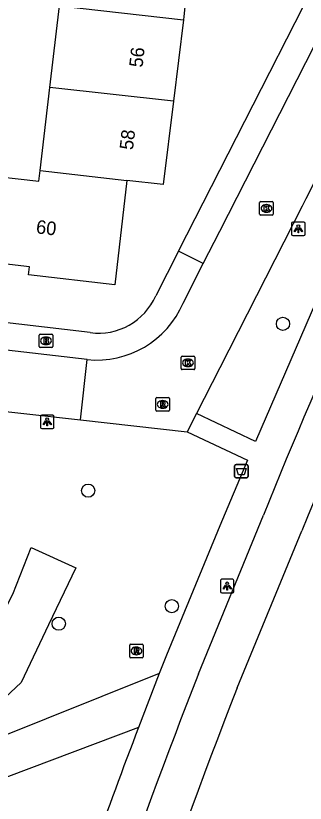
# Model space of a CAD drawing. Extents: x 161243 to 161752, y 384138 to 384885.
# Drawn here: x 161484.9 to 161506.3, y 384311.1 to 384369.4 of the extents above; entities that cross this region are included whole.
import ezdxf

# ---------------------------------------------------------------- set-up
doc = ezdxf.new("R2010")
doc.units = 0
for name, color, linetype in [('IMGEO_Afvalbak', 7, 'Continuous'), ('IMGEO_Boom', 7, 'Continuous'), ('IMGEO_Brandkraan', 7, 'Continuous'), ('IMGEO_Fietspad_gesloten', 7, 'Continuous'), ('IMGEO_Groenvoorziening', 7, 'Continuous'), ('IMGEO_Kolk', 7, 'Continuous'), ('IMGEO_Lichtpunt', 7, 'Continuous'), ('IMGEO_Pand', 7, 'Continuous'), ('IMGEO_Pand_nummerreeks', 7, 'Continuous'), ('IMGEO_Parkeervlak_open', 7, 'Continuous'), ('IMGEO_Rijbaan_lokaal_gesloten', 7, 'Continuous'), ('IMGEO_Rijbaan_lokaal_open', 7, 'Continuous'), ('IMGEO_Rioolput', 7, 'Continuous'), ('IMGEO_Voetpad_open', 7, 'Continuous')]:
    doc.layers.add(name, color=color, linetype=linetype)

msp = doc.modelspace()

# ---------------------------------------------------------------- linework, layer by layer
at = {"layer": 'IMGEO_Afvalbak'}
for p, q in [((161501.203, 384336.168), (161501.993, 384336.168)), ((161501.993, 384336.168), (161501.203, 384336.168)), ((161501.103, 384335.268), (161501.103, 384336.068)), ((161501.103, 384336.068), (161501.103, 384335.268)), ((161502.093, 384336.068), (161502.093, 384335.268)), ((161502.093, 384335.268), (161502.093, 384336.068)), ((161501.993, 384335.168), (161501.203, 384335.168)), ((161501.203, 384335.168), (161501.993, 384335.168))]:
    msp.add_line(p, q, dxfattribs=at)
msp.add_lwpolyline([(161501.246, 384335.882), (161501.95, 384335.882), (161501.801, 384335.412), (161501.395, 384335.412), (161501.246, 384335.882)], dxfattribs=at)
for centre, start, end in [((161501.203, 384336.068), 90, 180), ((161501.203, 384336.068), 90, 180), ((161501.993, 384336.068), 0, 90), ((161501.993, 384336.068), 360, 90), ((161501.203, 384335.268), 180, 270), ((161501.203, 384335.268), 180, 270), ((161501.993, 384335.268), 270, 0), ((161501.993, 384335.268), 270, 0)]:
    msp.add_arc(centre, 0.1, start, end, dxfattribs=at)
at = {"layer": 'IMGEO_Boom'}
for centre in [(161504.673, 384346.583), (161490.279, 384334.23), (161496.455, 384325.679), (161488.101, 384324.381)]:
    msp.add_circle(centre, 0.489, dxfattribs=at)
at = {"layer": 'IMGEO_Brandkraan'}
for p, q in [((161486.654, 384344.898), (161486.654, 384345.75)), ((161486.729, 384345.824), (161487.581, 384345.824)), ((161487.142, 384345.604), (161487.167, 384345.604)), ((161487.655, 384345.75), (161487.655, 384344.898)), ((161487.165, 384345.044), (161487.14, 384345.044)), ((161487.581, 384344.824), (161486.729, 384344.824))]:
    msp.add_line(p, q, dxfattribs=at)
for points in [[(161486.654, 384344.898), (161486.654, 384345.75)], [(161486.729, 384345.824), (161487.581, 384345.824)], [(161487.002, 384345.524), (161487.002, 384345.124), (161487.215, 384345.124)], [(161487.233, 384345.524), (161487.002, 384345.524)], [(161487.181, 384345.443), (161487.127, 384345.443), (161487.127, 384345.367)], [(161487.655, 384345.75), (161487.655, 384344.898)], [(161487.127, 384345.367), (161487.18, 384345.367)], [(161487.189, 384345.291), (161487.127, 384345.291), (161487.127, 384345.21)], [(161487.127, 384345.21), (161487.189, 384345.21)], [(161487.581, 384344.824), (161486.729, 384344.824)]]:
    msp.add_lwpolyline(points, dxfattribs=at)
for centre, radius, start, end in [((161486.731, 384345.748), 0.0765, 91.55205, 178.44795), ((161486.731, 384345.748), 0.0765, 91.55205, 178.44795), ((161487.182, 384345.405), 0.0379, 267.82845, 90.93552), ((161487.237, 384345.379), 0.145, 59.4692, 91.53667), ((161487.262, 384345.426), 0.0922, 285.51372, 58.15012), ((161487.579, 384345.748), 0.0765, 1.55205, 88.44795), ((161487.579, 384345.748), 0.0765, 1.55205, 88.44795), ((161486.731, 384344.9), 0.0765, 181.55205, 268.44795), ((161486.731, 384344.9), 0.0765, 181.55205, 268.44795), ((161487.19, 384345.25), 0.0404, 269.87594, 90.50774), ((161487.221, 384345.375), 0.251, 268.66757, 293.53466), ((161487.267, 384345.234), 0.105, 301.31148, 78.98903), ((161487.579, 384344.9), 0.0765, 271.55205, 358.44795), ((161487.579, 384344.9), 0.0765, 271.55205, 358.44795)]:
    msp.add_arc(centre, radius, start, end, dxfattribs=at)
for centre, major_axis, ratio, start_param, end_param in [((161487.141, 384345.324), (-0.387, 0.002), 0.722429, 4.712389, 7.853982), ((161487.166, 384345.324), (-0.39, 0.002), 0.717154, 1.570796, 4.712389)]:
    msp.add_ellipse(centre, major_axis=major_axis, ratio=ratio, start_param=start_param, end_param=end_param, dxfattribs=at)
at = {"layer": 'IMGEO_Fietspad_gesloten'}
for points in [[(161498.421, 384320.674), (161503.228, 384332.423)], [(161501.29, 384319.627), (161506.068, 384331.252)]]:
    msp.add_lwpolyline(points, dxfattribs=at)
for centre, radius, start, end in [((161887.469, 384177.749), 414.204, 153.12097, 158.07301), ((161885.987, 384179.087), 409.259, 153.19423, 158.17289), ((162043.129, 384109.325), 584.273, 158.793501, 162.628481), ((162039.774, 384110.274), 577.749, 158.754785, 167.348346)]:
    msp.add_arc(centre, radius, start, end, dxfattribs=at)
at = {"layer": 'IMGEO_Groenvoorziening'}
msp.add_lwpolyline([(161470.006, 384315.1), (161477.282, 384317.376), (161480.989, 384319.99), (161482.257, 384321.848), (161484.717, 384326.566), (161486.057, 384330.033), (161489.36, 384328.528), (161487.354, 384324.306), (161485.323, 384320.031), (161483.727, 384318.556), (161477.373, 384315.107), (161470.293, 384313.473), (161463.848, 384312.52), (161458.031, 384313.16), (161455.665, 384312.818), (161451.642, 384312.465), (161447.518, 384311.722)], dxfattribs=at)
at = {"layer": 'IMGEO_Kolk'}
for p, q in [((161502.951, 384354.704), (161502.951, 384355.556)), ((161503.026, 384355.63), (161503.878, 384355.63)), ((161503.439, 384355.41), (161503.464, 384355.41)), ((161503.952, 384355.556), (161503.952, 384354.704)), ((161503.462, 384354.85), (161503.437, 384354.85)), ((161503.878, 384354.63), (161503.026, 384354.63)), ((161497.15, 384343.265), (161497.15, 384344.117)), ((161497.225, 384344.191), (161498.077, 384344.191)), ((161497.638, 384343.971), (161497.663, 384343.971)), ((161498.151, 384344.117), (161498.151, 384343.265)), ((161498.077, 384343.191), (161497.225, 384343.191)), ((161497.661, 384343.411), (161497.636, 384343.411))]:
    msp.add_line(p, q, dxfattribs=at)
for points in [[(161502.951, 384354.704), (161502.951, 384355.556)], [(161503.026, 384355.63), (161503.878, 384355.63)], [(161503.952, 384355.556), (161503.952, 384354.704)], [(161503.272, 384355.33), (161503.395, 384355.33), (161503.395, 384355.179), (161503.525, 384355.33), (161503.689, 384355.33), (161503.543, 384355.179), (161503.696, 384354.93), (161503.544, 384354.93), (161503.459, 384355.094), (161503.395, 384355.027), (161503.395, 384354.93), (161503.272, 384354.93), (161503.272, 384355.33)], [(161503.878, 384354.63), (161503.026, 384354.63)], [(161497.15, 384343.265), (161497.15, 384344.117)], [(161497.225, 384344.191), (161498.077, 384344.191)], [(161497.471, 384343.891), (161497.594, 384343.891), (161497.594, 384343.74), (161497.724, 384343.891), (161497.888, 384343.891), (161497.742, 384343.74), (161497.895, 384343.491), (161497.743, 384343.491), (161497.658, 384343.655), (161497.594, 384343.588), (161497.594, 384343.491), (161497.471, 384343.491), (161497.471, 384343.891)], [(161498.151, 384344.117), (161498.151, 384343.265)], [(161498.077, 384343.191), (161497.225, 384343.191)]]:
    msp.add_lwpolyline(points, dxfattribs=at)
for centre, start, end in [((161503.028, 384355.554), 91.55205, 178.44795), ((161503.028, 384355.554), 91.55205, 178.44795), ((161503.876, 384355.554), 1.55205, 88.44795), ((161503.876, 384355.554), 1.55205, 88.44795), ((161503.028, 384354.706), 181.55205, 268.44795), ((161503.028, 384354.706), 181.55205, 268.44795), ((161503.876, 384354.706), 271.55205, 358.44795), ((161503.876, 384354.706), 271.55205, 358.44795), ((161497.227, 384344.115), 91.55205, 178.44795), ((161497.227, 384344.115), 91.55205, 178.44795), ((161498.075, 384344.115), 1.55205, 88.44795), ((161498.075, 384344.115), 1.55205, 88.44795), ((161497.227, 384343.267), 181.55205, 268.44795), ((161497.227, 384343.267), 181.55205, 268.44795), ((161498.075, 384343.267), 271.55205, 358.44795), ((161498.075, 384343.267), 271.55205, 358.44795)]:
    msp.add_arc(centre, 0.0765, start, end, dxfattribs=at)
for centre, major_axis, ratio, start_param, end_param in [((161503.438, 384355.13), (-0.387, 0.002), 0.722429, 4.712389, 7.853982), ((161503.463, 384355.13), (-0.39, 0.002), 0.717154, 1.570796, 4.712389), ((161497.637, 384343.691), (-0.387, 0.002), 0.722429, 4.712389, 7.853982), ((161497.662, 384343.691), (-0.39, 0.002), 0.717154, 1.570796, 4.712389)]:
    msp.add_ellipse(centre, major_axis=major_axis, ratio=ratio, start_param=start_param, end_param=end_param, dxfattribs=at)
at = {"layer": 'IMGEO_Lichtpunt'}
for p, q in [((161505.311, 384354.016), (161505.311, 384353.209)), ((161505.311, 384354.016), (161505.311, 384353.209)), ((161506.213, 384354.111), (161505.405, 384354.111)), ((161506.213, 384354.111), (161505.405, 384354.111)), ((161506.307, 384353.209), (161506.307, 384354.016)), ((161506.307, 384353.209), (161506.307, 384354.016)), ((161505.405, 384353.115), (161506.213, 384353.115)), ((161505.405, 384353.115), (161506.213, 384353.115)), ((161486.754, 384339.725), (161486.754, 384338.918)), ((161486.754, 384339.725), (161486.754, 384338.918)), ((161487.656, 384339.82), (161486.848, 384339.82)), ((161487.656, 384339.82), (161486.848, 384339.82)), ((161487.75, 384338.918), (161487.75, 384339.725)), ((161487.75, 384338.918), (161487.75, 384339.725)), ((161486.848, 384338.824), (161487.656, 384338.824)), ((161486.848, 384338.824), (161487.656, 384338.824)), ((161500.055, 384327.572), (161500.055, 384326.765)), ((161500.055, 384327.572), (161500.055, 384326.765)), ((161500.957, 384327.667), (161500.149, 384327.667)), ((161500.957, 384327.667), (161500.149, 384327.667)), ((161501.051, 384326.765), (161501.051, 384327.572)), ((161501.051, 384326.765), (161501.051, 384327.572)), ((161500.149, 384326.671), (161500.957, 384326.671)), ((161500.149, 384326.671), (161500.957, 384326.671))]:
    msp.add_line(p, q, dxfattribs=at)
for points in [[(161505.685, 384353.68), (161505.724, 384353.652), (161505.536, 384353.39), (161505.498, 384353.417), (161505.685, 384353.68)], [(161505.787, 384353.632), (161505.834, 384353.632), (161505.834, 384353.31), (161505.787, 384353.31), (161505.787, 384353.632)], [(161505.897, 384353.652), (161505.935, 384353.679), (161506.122, 384353.417), (161506.083, 384353.389), (161505.897, 384353.652)], [(161487.128, 384339.389), (161487.167, 384339.361), (161486.979, 384339.099), (161486.941, 384339.126), (161487.128, 384339.389)], [(161487.23, 384339.341), (161487.277, 384339.341), (161487.277, 384339.019), (161487.23, 384339.019), (161487.23, 384339.341)], [(161487.34, 384339.361), (161487.378, 384339.388), (161487.565, 384339.126), (161487.526, 384339.098), (161487.34, 384339.361)], [(161500.429, 384327.236), (161500.468, 384327.208), (161500.28, 384326.946), (161500.242, 384326.973), (161500.429, 384327.236)], [(161500.531, 384327.188), (161500.578, 384327.188), (161500.578, 384326.866), (161500.531, 384326.866), (161500.531, 384327.188)], [(161500.641, 384327.208), (161500.679, 384327.235), (161500.866, 384326.973), (161500.827, 384326.945), (161500.641, 384327.208)]]:
    msp.add_lwpolyline(points, dxfattribs=at)
for centre in [(161505.81, 384353.814), (161487.253, 384339.523), (161500.554, 384327.37)]:
    msp.add_circle(centre, 0.0994, dxfattribs=at)
for centre, start, end in [((161505.405, 384354.016), 90, 180), ((161505.405, 384354.016), 90, 180), ((161506.213, 384354.016), 0, 90), ((161506.213, 384354.016), 0, 90), ((161505.405, 384353.209), 180, 270), ((161505.405, 384353.209), 180, 270), ((161506.213, 384353.209), 270, 0), ((161506.213, 384353.209), 270, 360), ((161486.848, 384339.725), 90, 180), ((161486.848, 384339.725), 90, 180), ((161487.656, 384339.725), 0, 90), ((161487.656, 384339.725), 0, 90), ((161486.848, 384338.918), 180, 270), ((161486.848, 384338.918), 180, 270), ((161487.656, 384338.918), 270, 0), ((161487.656, 384338.918), 270, 360), ((161500.149, 384327.572), 90, 180), ((161500.149, 384327.572), 90, 180), ((161500.957, 384327.572), 0, 90), ((161500.957, 384327.572), 0, 90), ((161500.149, 384326.765), 180, 270), ((161500.149, 384326.765), 180, 270), ((161500.957, 384326.765), 270, 0), ((161500.957, 384326.765), 270, 360)]:
    msp.add_arc(centre, 0.0946, start, end, dxfattribs=at)
at = {"layer": 'IMGEO_Pand'}
for points in [[(161488.879, 384376.277), (161492.977, 384375.8), (161497.943, 384375.221), (161497.358, 384369.338), (161497.328, 384369.093)], [(161487.449, 384364.089), (161488.158, 384370.128)], [(161488.158, 384370.128), (161497.328, 384369.093)], [(161497.328, 384369.093), (161496.586, 384363.058)], [(161486.727, 384357.934), (161487.449, 384364.089)], [(161496.586, 384363.058), (161487.449, 384364.089)], [(161496.586, 384363.058), (161495.828, 384356.898), (161493.144, 384357.205)], [(161482.243, 384357.65), (161486.633, 384357.135), (161486.727, 384357.934)], [(161486.727, 384357.934), (161493.144, 384357.205)], [(161493.144, 384357.205), (161492.248, 384349.474), (161485.872, 384350.207), (161485.928, 384350.807), (161481.501, 384351.329)]]:
    msp.add_lwpolyline(points, dxfattribs=at)
at = {"layer": 'IMGEO_Parkeervlak_open'}
msp.add_lwpolyline([(161496.955, 384351.974), (161500, 384357.957), (161508.657, 384374.966)], dxfattribs=at)
at = {"layer": 'IMGEO_Rijbaan_lokaal_gesloten'}
for points in [[(161495.528, 384320.69), (161466.078, 384308.877)], [(161495.528, 384320.69), (161493.996, 384316.698)], [(161493.996, 384316.698), (161468.357, 384307.022)]]:
    msp.add_lwpolyline(points, dxfattribs=at)
msp.add_arc((162044.643, 384105.26), 574.475, 156.600365, 160.880508, dxfattribs=at)
at = {"layer": 'IMGEO_Rijbaan_lokaal_open'}
for points in [[(161498.781, 384351.045), (161500, 384353.441), (161510.808, 384374.674)], [(161512.251, 384367.418), (161506.367, 384355.848), (161506.092, 384355.306), (161500, 384343.328), (161498.277, 384339.941)], [(161497.294, 384348.121), (161498.781, 384351.045)], [(161490.204, 384343.929), (161438.91, 384349.892)], [(161489.705, 384339.472), (161490.204, 384343.929)], [(161476.463, 384340.955), (161489.705, 384339.472)], [(161498.277, 384339.941), (161497.59, 384338.589)], [(161489.705, 384339.472), (161497.59, 384338.589)]]:
    msp.add_lwpolyline(points, dxfattribs=at)
msp.add_arc((161490.892, 384350.858), 6.963, 264.33204, 336.85581, dxfattribs=at)
at = {"layer": 'IMGEO_Rioolput'}
for p, q in [((161495.277, 384340.192), (161495.277, 384341.044)), ((161495.352, 384341.118), (161496.204, 384341.118)), ((161495.765, 384340.898), (161495.79, 384340.898)), ((161496.278, 384341.044), (161496.278, 384340.192)), ((161495.788, 384340.338), (161495.763, 384340.338)), ((161496.204, 384340.118), (161495.352, 384340.118)), ((161493.343, 384321.936), (161493.343, 384322.788)), ((161493.418, 384322.862), (161494.27, 384322.862)), ((161494.344, 384322.788), (161494.344, 384321.936)), ((161493.831, 384322.642), (161493.856, 384322.642)), ((161494.27, 384321.862), (161493.418, 384321.862)), ((161493.854, 384322.082), (161493.829, 384322.082))]:
    msp.add_line(p, q, dxfattribs=at)
for points in [[(161495.277, 384340.192), (161495.277, 384341.044)], [(161495.352, 384341.118), (161496.204, 384341.118)], [(161495.866, 384340.816), (161495.614, 384340.818), (161495.614, 384340.418)], [(161496.278, 384341.044), (161496.278, 384340.192)], [(161495.614, 384340.418), (161495.738, 384340.418), (161495.738, 384340.58), (161495.749, 384340.58)], [(161495.792, 384340.737), (161495.738, 384340.737), (161495.738, 384340.656)], [(161495.738, 384340.656), (161495.79, 384340.656)], [(161495.796, 384340.551), (161495.867, 384340.418), (161496.007, 384340.418), (161495.942, 384340.544)], [(161496.204, 384340.118), (161495.352, 384340.118)], [(161493.343, 384321.936), (161493.343, 384322.788)], [(161493.418, 384322.862), (161494.27, 384322.862)], [(161494.344, 384322.788), (161494.344, 384321.936)], [(161493.932, 384322.56), (161493.68, 384322.562), (161493.68, 384322.162)], [(161493.68, 384322.162), (161493.804, 384322.162), (161493.804, 384322.324), (161493.815, 384322.324)], [(161493.858, 384322.481), (161493.804, 384322.481), (161493.804, 384322.4)], [(161493.804, 384322.4), (161493.856, 384322.4)], [(161493.862, 384322.295), (161493.933, 384322.162), (161494.073, 384322.162), (161494.008, 384322.288)], [(161494.27, 384321.862), (161493.418, 384321.862)]]:
    msp.add_lwpolyline(points, dxfattribs=at)
for centre, radius, start, end in [((161495.354, 384341.042), 0.0765, 91.55205, 178.44795), ((161495.354, 384341.042), 0.0765, 91.55205, 178.44795), ((161495.865, 384340.706), 0.109, 350.36119, 89.41601), ((161496.202, 384341.042), 0.0765, 1.55205, 88.44795), ((161496.202, 384341.042), 0.0765, 1.55205, 88.44795), ((161495.354, 384340.194), 0.0765, 181.55205, 268.44795), ((161495.354, 384340.194), 0.0765, 181.55205, 268.44795), ((161495.748, 384340.527), 0.0533, 26.02933, 88.69889), ((161495.774, 384340.845), 0.19, 274.7715, 282.96867), ((161495.798, 384340.641), 0.0964, 77.00612, 93.18647), ((161495.812, 384340.698), 0.0378, 276.66336, 79.67722), ((161495.863, 384340.706), 0.112, 277.58423, 350.98172), ((161495.847, 384340.491), 0.108, 29.51342, 73.79051), ((161496.202, 384340.194), 0.0765, 271.55205, 358.44795), ((161496.202, 384340.194), 0.0765, 271.55205, 358.44795), ((161493.42, 384322.786), 0.0765, 91.55205, 178.44795), ((161493.42, 384322.786), 0.0765, 91.55205, 178.44795), ((161494.268, 384322.786), 0.0765, 1.55205, 88.44795), ((161494.268, 384322.786), 0.0765, 1.55205, 88.44795), ((161493.814, 384322.271), 0.0533, 26.02933, 88.69889), ((161493.84, 384322.589), 0.19, 274.7715, 282.96867), ((161493.864, 384322.385), 0.0964, 77.00612, 93.18647), ((161493.878, 384322.442), 0.0378, 276.66336, 79.67722), ((161493.931, 384322.45), 0.109, 350.36119, 89.41601), ((161493.929, 384322.45), 0.112, 277.58423, 350.98172), ((161493.913, 384322.235), 0.108, 29.51342, 73.79051), ((161493.42, 384321.938), 0.0765, 181.55205, 268.44795), ((161493.42, 384321.938), 0.0765, 181.55205, 268.44795), ((161494.268, 384321.938), 0.0765, 271.55205, 358.44795), ((161494.268, 384321.938), 0.0765, 271.55205, 358.44795)]:
    msp.add_arc(centre, radius, start, end, dxfattribs=at)
for centre, major_axis, ratio, start_param, end_param in [((161495.764, 384340.618), (-0.387, 0.002), 0.722429, 4.712389, 7.853982), ((161495.789, 384340.618), (-0.39, 0.002), 0.717154, 1.570796, 4.712389), ((161493.83, 384322.362), (-0.387, 0.002), 0.722429, 4.712389, 7.853982), ((161493.855, 384322.362), (-0.39, 0.002), 0.717154, 1.570796, 4.712389)]:
    msp.add_ellipse(centre, major_axis=major_axis, ratio=ratio, start_param=start_param, end_param=end_param, dxfattribs=at)
at = {"layer": 'IMGEO_Voetpad_open'}
for points in [[(161512.251, 384367.418), (161515.439, 384365.834), (161508.855, 384352.164), (161508.579, 384351.624), (161502.638, 384337.876), (161498.277, 384339.941)], [(161490.429, 384345.932), (161394.009, 384357.23)], [(161496.955, 384351.974), (161495.272, 384348.667)], [(161498.781, 384351.045), (161496.955, 384351.974)], [(161497.59, 384338.589), (161502.043, 384336.478), (161500, 384331.628), (161496.059, 384322.051), (161495.528, 384320.69)]]:
    msp.add_lwpolyline(points, dxfattribs=at)
for centre, radius, start, end in [((161491.045, 384350.497), 4.606, 262.31377, 336.5959), ((162024.399, 384115.559), 567.26, 159.23233, 160.21693)]:
    msp.add_arc(centre, radius, start, end, dxfattribs=at)

# ---------------------------------------------------------------- texts
at = {"layer": 'IMGEO_Pand_nummerreeks'}
for s, rotation, p in [('56', 83.41556, (161494.288, 384365.528)), ('58', 83.41556, (161493.583, 384359.422)), ('60', 353.27643, (161486.386, 384353.291))]:
    msp.add_text(s, height=1, rotation=rotation, dxfattribs=at).set_placement(p)

doc.saveas('drawing.dxf')
